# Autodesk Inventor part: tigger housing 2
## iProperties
Created: 2006-04
Part Number: tigger housing 2
Document SubType Name: Modeling
Designer: Калинин
Author: Калинин
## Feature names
1. Выдавливание1 [Extrusion]
2. Выдавливание2 [Extrusion]
3. Выдавливание3 [Extrusion]
4. Выдавливание4 [Extrusion]
5. Выдавливание5 [Extrusion]
6. Выдавливание6 [Extrusion]
7. Фаска1 [Chamfer]
8. Сопряжение1 [Fillet]
9. Сопряжение2 [Fillet]
10. Сопряжение3 [Fillet]
11. Отверстие1 [Hole]
12. Выдавливание7 [Extrusion]
